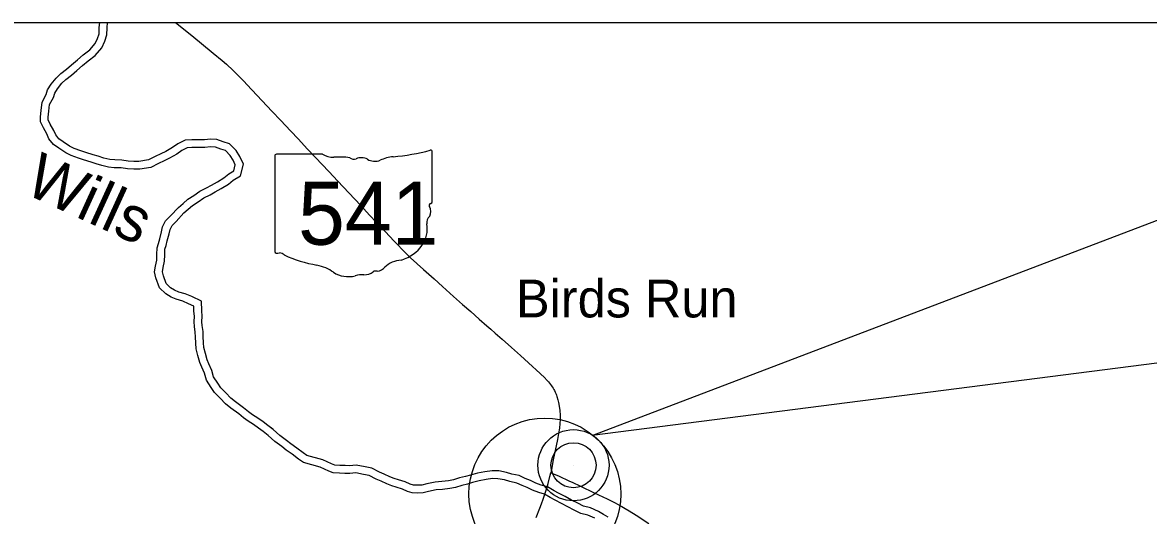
# Model space of a CAD drawing. Extents: x -12.1 to 34, y 0 to 22.
# Drawn here: x 3.941 to 6.151, y 19.34 to 20.306 of the extents above; entities that cross this region are included whole.
import ezdxf

# ---------------------------------------------------------------- set-up
doc = ezdxf.new("R2010")
doc.units = 0
for name, color, linetype in [('BR_P_Gen_Text', 7, 'Continuous'), ('Default', 7, 'Continuous'), ('GM_X_Major_River', 7, 'Continuous'), ('GM_X_Major_River_Text', 7, 'Continuous'), ('GM_X_State_Route', 7, 'Continuous'), ('GM_X_State_Shield', 7, 'Continuous'), ('GM_X_Unincorporated', 7, 'Continuous'), ('GM_X_Unincorporated_Location', 7, 'Continuous'), ('GM_X_Unincorporated_Text', 7, 'Continuous'), ('SH_Text', 7, 'Continuous')]:
    doc.layers.add(name, color=color, linetype=linetype)

msp = doc.modelspace()

# ---------------------------------------------------------------- linework, layer by layer
at = {"layer": 'BR_P_Gen_Text'}
msp.add_lwpolyline([(6.2488, 19.9493), (6.2488, 19.649), (5.0586, 19.4964)], close=True, dxfattribs=at)
at = {"layer": 'Default'}
msp.add_circle((4.9659, 19.3816), 0.149, dxfattribs=at)
at = {"layer": 'GM_X_Major_River'}
for points in [[(4.0372, 20.2236), (4.0485, 20.2333), (4.0601, 20.243), (4.0727, 20.253), (4.0836, 20.2649), (4.0881, 20.2748), (4.0909, 20.2844), (4.0914, 20.2965), (4.0922, 20.3063)], [(4.0472, 20.2121), (4.0584, 20.2217), (4.0697, 20.2312), (4.0832, 20.2419), (4.0965, 20.2564), (4.1025, 20.2696), (4.106, 20.2819), (4.1067, 20.2956), (4.1074, 20.3063)], [(4.0473, 20.2122), (4.0584, 20.2217), (4.0697, 20.2312), (4.0832, 20.2419), (4.0965, 20.2564), (4.1025, 20.2696), (4.106, 20.2819), (4.1067, 20.2956), (4.1074, 20.3063)], [(4.4228, 19.4967), (4.4131, 19.504), (4.4038, 19.5107), (4.3942, 19.5177), (4.3835, 19.5243), (4.3746, 19.531), (4.3653, 19.5387), (4.3496, 19.5503), (4.3393, 19.5583), (4.3285, 19.5696), (4.3178, 19.5805), (4.3113, 19.5907), (4.3016, 19.6051), (4.2979, 19.6186), (4.2925, 19.6306), (4.2885, 19.6398), (4.2848, 19.6536), (4.2819, 19.6663), (4.2807, 19.6773), (4.2802, 19.6897), (4.2798, 19.699), (4.2783, 19.7103), (4.2775, 19.7192), (4.2781, 19.7302), (4.2773, 19.7405), (4.2772, 19.75), (4.2668, 19.7549), (4.2551, 19.7597), (4.2423, 19.7635), (4.2323, 19.768), (4.222, 19.774), (4.2098, 19.7859), (4.2026, 19.8053), (4.2, 19.8174), (4.202, 19.8288), (4.2044, 19.8401), (4.2046, 19.8511), (4.2052, 19.8643), (4.2079, 19.8732), (4.21, 19.882), (4.2137, 19.8956), (4.2158, 19.9055), (4.2217, 19.9173), (4.2315, 19.927), (4.2469, 19.9438), (4.256, 19.9517), (4.2655, 19.9599), (4.2772, 19.9671), (4.2888, 19.9754), (4.3018, 19.9819), (4.3117, 19.9873), (4.3233, 19.9938), (4.336, 20.0014), (4.3455, 20.0093), (4.3553, 20.0154), (4.3584, 20.0272), (4.3541, 20.0364), (4.3483, 20.0455), (4.339, 20.055), (4.3298, 20.0581), (4.3194, 20.0619), (4.3099, 20.0622), (4.2985, 20.0613), (4.2858, 20.0612), (4.2734, 20.0611), (4.2642, 20.0606), (4.2533, 20.0552), (4.2434, 20.0484), (4.229, 20.0401), (4.2187, 20.035), (4.2075, 20.0296), (4.1926, 20.0223), (4.1707, 20.0186), (4.159, 20.0185), (4.1466, 20.0194), (4.1342, 20.021), (4.1207, 20.0216), (4.1097, 20.0226), (4.0966, 20.026), (4.0852, 20.0294), (4.0753, 20.0322), (4.0607, 20.037), (4.0504, 20.0401), (4.0362, 20.0456), (4.0255, 20.0508), (4.0123, 20.0599), (4.0016, 20.0669), (3.9926, 20.0781), (3.9886, 20.088), (3.9818, 20.1), (3.976, 20.1117), (3.9759, 20.1212), (3.9772, 20.134), (3.9792, 20.15), (3.9872, 20.1653), (3.9899, 20.1742), (3.9969, 20.1853), (4.0067, 20.1974), (4.0158, 20.2064), (4.0274, 20.215), (4.0372, 20.2236)], [(4.432, 19.5088), (4.4222, 19.5163), (4.4128, 19.523), (4.4027, 19.5303), (4.3921, 19.5369), (4.384, 19.5429), (4.3747, 19.5507), (4.3588, 19.5624), (4.3495, 19.5696), (4.3395, 19.5802), (4.3298, 19.59), (4.3241, 19.599), (4.3157, 19.6115), (4.3123, 19.6238), (4.3064, 19.6368), (4.3029, 19.6448), (4.2996, 19.6573), (4.2969, 19.6689), (4.2959, 19.6784), (4.2955, 19.6904), (4.295, 19.7003), (4.2934, 19.712), (4.2927, 19.7194), (4.2933, 19.7304), (4.2925, 19.7411), (4.2923, 19.7597), (4.273, 19.7688), (4.2602, 19.7741), (4.2476, 19.7778), (4.2393, 19.7816), (4.2313, 19.7862), (4.2229, 19.7944), (4.2172, 19.8096), (4.2155, 19.8177), (4.217, 19.8259), (4.2196, 19.8384), (4.2198, 19.8506), (4.2203, 19.8616), (4.2227, 19.8692), (4.2247, 19.8783), (4.2286, 19.892), (4.2303, 19.9005), (4.2342, 19.9082), (4.2425, 19.9164), (4.2576, 19.9329), (4.266, 19.9402), (4.2746, 19.9477), (4.2856, 19.9545), (4.2967, 19.9623), (4.3089, 19.9685), (4.3191, 19.974), (4.3309, 19.9807), (4.3448, 19.989), (4.3544, 19.997), (4.3685, 20.0057), (4.3746, 20.0287), (4.3675, 20.0437), (4.3603, 20.055), (4.3473, 20.0683), (4.3348, 20.0725), (4.3224, 20.077), (4.3095, 20.0774), (4.2979, 20.0765), (4.2856, 20.0764), (4.273, 20.0763), (4.2603, 20.0757), (4.2455, 20.0683), (4.2352, 20.0612), (4.2218, 20.0535), (4.212, 20.0487), (4.2008, 20.0433), (4.1879, 20.037), (4.1693, 20.0338), (4.1595, 20.0337), (4.1482, 20.0345), (4.1355, 20.0362), (4.1217, 20.0368), (4.1123, 20.0376), (4.1007, 20.0406), (4.0895, 20.044), (4.0797, 20.0467), (4.0653, 20.0515), (4.0554, 20.0545), (4.0423, 20.0595), (4.0332, 20.064), (4.0208, 20.0725), (4.012, 20.0783), (4.0059, 20.0859), (4.0024, 20.0947), (3.9952, 20.1072), (3.9912, 20.1153), (3.9912, 20.1206), (3.9923, 20.1323), (3.994, 20.1454), (4.0013, 20.1595), (4.0039, 20.1678), (4.0093, 20.1764), (4.018, 20.1872), (4.0258, 20.1948), (4.037, 20.2032), (4.0473, 20.2122)], [(4.4325, 19.5084), (4.4222, 19.5163), (4.4128, 19.523), (4.4027, 19.5303), (4.3921, 19.5369), (4.384, 19.5429), (4.3747, 19.5507), (4.3588, 19.5624), (4.3495, 19.5696), (4.3395, 19.5802), (4.3298, 19.59), (4.3241, 19.599), (4.3157, 19.6115), (4.3123, 19.6238), (4.3064, 19.6368), (4.3029, 19.6448), (4.2996, 19.6573), (4.2969, 19.6689), (4.2959, 19.6784), (4.2955, 19.6904), (4.295, 19.7003), (4.2934, 19.712), (4.2927, 19.7194), (4.2933, 19.7304), (4.2925, 19.7411), (4.2923, 19.7597), (4.273, 19.7688), (4.2602, 19.7741), (4.2476, 19.7778), (4.2393, 19.7816), (4.2313, 19.7862), (4.2229, 19.7944), (4.2172, 19.8096), (4.2155, 19.8177), (4.217, 19.8259), (4.2196, 19.8384), (4.2198, 19.8506), (4.2203, 19.8616), (4.2227, 19.8692), (4.2247, 19.8783), (4.2286, 19.892), (4.2303, 19.9005), (4.2342, 19.9082), (4.2425, 19.9164), (4.2576, 19.9329), (4.266, 19.9402), (4.2746, 19.9477), (4.2856, 19.9545), (4.2967, 19.9623), (4.3089, 19.9685), (4.3191, 19.974), (4.3309, 19.9807), (4.3448, 19.989), (4.3544, 19.997), (4.3685, 20.0057), (4.3746, 20.0287), (4.3675, 20.0437), (4.3603, 20.055), (4.3473, 20.0683), (4.3348, 20.0725), (4.3224, 20.077), (4.3095, 20.0774), (4.2979, 20.0765), (4.2856, 20.0764), (4.273, 20.0763), (4.2603, 20.0757), (4.2455, 20.0683), (4.2352, 20.0612), (4.2218, 20.0535), (4.212, 20.0487), (4.2008, 20.0433), (4.1879, 20.037), (4.1693, 20.0338), (4.1595, 20.0337), (4.1482, 20.0345), (4.1355, 20.0362), (4.1217, 20.0368), (4.1123, 20.0376), (4.1007, 20.0406), (4.0895, 20.044), (4.0797, 20.0467), (4.0653, 20.0515), (4.0554, 20.0545), (4.0423, 20.0595), (4.0332, 20.064), (4.0208, 20.0725), (4.012, 20.0783), (4.0059, 20.0859), (4.0024, 20.0947), (3.9952, 20.1072), (3.9912, 20.1153), (3.9912, 20.1206), (3.9923, 20.1323), (3.994, 20.1454), (4.0013, 20.1595), (4.0039, 20.1678), (4.0093, 20.1764), (4.018, 20.1872), (4.0258, 20.1948), (4.037, 20.2032), (4.0473, 20.2122)], [(5.0638, 19.3341), (5.0503, 19.3403), (5.0368, 19.3434), (5.0237, 19.35), (5.0108, 19.3563), (4.9987, 19.3632), (4.9859, 19.3695), (4.9766, 19.3747), (4.9649, 19.3814), (4.9539, 19.3845), (4.9418, 19.3889), (4.9315, 19.3945), (4.9211, 19.3983), (4.9108, 19.4032), (4.8973, 19.4059), (4.887, 19.4094), (4.8739, 19.4117), (4.8633, 19.412), (4.8505, 19.4104), (4.8371, 19.4074), (4.824, 19.4041), (4.8138, 19.4012), (4.8028, 19.3986), (4.7904, 19.3946), (4.7791, 19.3927), (4.7653, 19.3907), (4.7529, 19.3896), (4.7377, 19.3869), (4.7268, 19.384), (4.7151, 19.3835), (4.7055, 19.3841), (4.6963, 19.3865), (4.6863, 19.391), (4.6742, 19.3948), (4.6653, 19.3979), (4.6561, 19.4014), (4.6444, 19.4066), (4.6351, 19.4108), (4.6212, 19.4177), (4.6099, 19.4201), (4.595, 19.4231), (4.5833, 19.422), (4.5734, 19.4222), (4.5631, 19.4225), (4.5507, 19.4234), (4.5418, 19.4265), (4.5251, 19.4342), (4.492, 19.4434), (4.4827, 19.4497), (4.4699, 19.4595), (4.4585, 19.4676), (4.4495, 19.4746), (4.4363, 19.4847), (4.4228, 19.4967)], [(5.0901, 19.3363), (5.0809, 19.3416), (5.071, 19.3475), (5.0553, 19.3548), (5.042, 19.3578), (5.0304, 19.3636), (5.018, 19.3697), (5.0059, 19.3767), (4.993, 19.383), (4.9842, 19.388), (4.9708, 19.3955), (4.9586, 19.3989), (4.9481, 19.4029), (4.9378, 19.4084), (4.9271, 19.4124), (4.9157, 19.4178), (4.9013, 19.4206), (4.8908, 19.4241), (4.8754, 19.4269), (4.8625, 19.4272), (4.848, 19.4254), (4.8336, 19.4223), (4.82, 19.4188), (4.8099, 19.4159), (4.7987, 19.4133), (4.7868, 19.4094), (4.7768, 19.4077), (4.7636, 19.4059), (4.7509, 19.4047), (4.7344, 19.4018), (4.7245, 19.3991), (4.7153, 19.3988), (4.7079, 19.3992), (4.7014, 19.4009), (4.6918, 19.4053), (4.679, 19.4093), (4.6705, 19.4122), (4.6619, 19.4155), (4.6506, 19.4205), (4.6417, 19.4245), (4.6263, 19.4322), (4.613, 19.435), (4.5957, 19.4385), (4.5827, 19.4372), (4.5737, 19.4374), (4.5638, 19.4377), (4.5538, 19.4384), (4.5475, 19.4407), (4.5303, 19.4485), (4.4985, 19.4574), (4.4917, 19.4621), (4.4789, 19.4718), (4.4676, 19.4798), (4.4589, 19.4866), (4.446, 19.4965), (4.4325, 19.5084)], [(5.0901, 19.3363), (5.0809, 19.3416), (5.071, 19.3475), (5.0553, 19.3548), (5.042, 19.3578), (5.0304, 19.3636), (5.018, 19.3697), (5.0059, 19.3767), (4.993, 19.383), (4.9842, 19.388), (4.9708, 19.3955), (4.9586, 19.3989), (4.9481, 19.4029), (4.9378, 19.4084), (4.9271, 19.4124), (4.9157, 19.4178), (4.9013, 19.4206), (4.8908, 19.4241), (4.8754, 19.4269), (4.8625, 19.4272), (4.848, 19.4254), (4.8336, 19.4223), (4.82, 19.4188), (4.8099, 19.4159), (4.7987, 19.4133), (4.7868, 19.4094), (4.7768, 19.4077), (4.7636, 19.4059), (4.7509, 19.4047), (4.7344, 19.4018), (4.7245, 19.3991), (4.7153, 19.3988), (4.7079, 19.3992), (4.7014, 19.4009), (4.6918, 19.4053), (4.679, 19.4093), (4.6705, 19.4122), (4.6619, 19.4155), (4.6506, 19.4205), (4.6417, 19.4245), (4.6263, 19.4322), (4.613, 19.435), (4.5957, 19.4385), (4.5827, 19.4372), (4.5737, 19.4374), (4.5638, 19.4377), (4.5538, 19.4384), (4.5475, 19.4407), (4.5303, 19.4485), (4.4985, 19.4574), (4.4917, 19.4621), (4.4789, 19.4718), (4.4676, 19.4798), (4.4589, 19.4866), (4.446, 19.4965), (4.4328, 19.5081)]]:
    msp.add_lwpolyline(points, dxfattribs=at)
at = {"layer": 'GM_X_State_Route'}
for points in [[(4.2413, 20.3063), (4.2728, 20.2807), (4.3151, 20.2461), (4.3327, 20.2316), (4.3411, 20.2244), (4.3539, 20.2124), (4.3626, 20.2039), (4.3708, 20.1956), (4.3752, 20.191), (4.3817, 20.1843), (4.4302, 20.1324), (4.4475, 20.1142), (4.4667, 20.094), (4.4822, 20.0773), (4.4997, 20.0585), (4.5156, 20.0416), (4.5418, 20.0142), (4.5598, 19.9951), (4.5814, 19.9723), (4.605, 19.9473), (4.622, 19.9288), (4.6358, 19.9139), (4.653, 19.8957), (4.6698, 19.8779), (4.6739, 19.8737), (4.6893, 19.8579), (4.703, 19.8445), (4.7143, 19.8341), (4.7154, 19.833), (4.7275, 19.8221), (4.7484, 19.8036), (4.7649, 19.7888), (4.7865, 19.7693), (4.8044, 19.7536), (4.8205, 19.7393), (4.8371, 19.7246), (4.8521, 19.7117), (4.8599, 19.7048), (4.8682, 19.6974), (4.8822, 19.6851), (4.9006, 19.669), (4.9183, 19.653), (4.9337, 19.6388), (4.9567, 19.6182), (4.9582, 19.6167), (4.9647, 19.6105), (4.9707, 19.6041), (4.973, 19.6017), (4.975, 19.5993), (4.9772, 19.5966), (4.979, 19.5941), (4.9805, 19.5918), (4.9821, 19.5892), (4.9834, 19.5869), (4.9846, 19.5846), (4.986, 19.5817), (4.9873, 19.5787), (4.9879, 19.5772)], [(4.9879, 19.5772), (4.9886, 19.5757), (4.9896, 19.5727), (4.9916, 19.5665), (4.9928, 19.5614), (4.9942, 19.5539), (4.9951, 19.5457), (4.9957, 19.5364), (4.9958, 19.532), (4.9957, 19.5276), (4.9954, 19.52), (4.9944, 19.5107), (4.9928, 19.5002), (4.9907, 19.4888), (4.9825, 19.4488), (4.9791, 19.43), (4.9779, 19.423)], [(4.9487, 19.3354), (4.9563, 19.354), (4.9592, 19.3621), (4.9627, 19.3717), (4.9659, 19.3816), (4.9696, 19.3933), (4.9721, 19.402), (4.976, 19.4161), (4.9779, 19.423)], [(4.9779, 19.423), (4.9925, 19.417), (5.0145, 19.4071), (5.0196, 19.4048), (5.0359, 19.3971), (5.0627, 19.3842), (5.088, 19.3722), (5.0999, 19.3661), (5.1123, 19.3595), (5.1315, 19.3485), (5.1454, 19.34), (5.1703, 19.3237)]]:
    msp.add_lwpolyline(points, dxfattribs=at)
at = {"layer": 'GM_X_State_Shield'}
for p, q in [((4.4359, 20.0449), (4.4359, 19.8573)), ((4.5295, 20.0481), (4.439, 20.0481)), ((4.7449, 19.9546), (4.7449, 20.0528)), ((4.7449, 19.9547), (4.7449, 19.9546))]:
    msp.add_line(p, q, dxfattribs=at)
for centre, major_axis, start_param, end_param in [((4.4395, 20.0453), (0.00358, 0), 1.712693, 3.28349), ((4.551, 20.0699), (0.0347, 0), 4.042523, 4.731795), ((4.5625, 19.9428), (0.1246, 0), 1.404758, 1.657858), ((4.6766, 19.9908), (0.0659, 0), 1.699011, 2.107814), ((4.6348, 20.3039), (0.3277, 0), 4.814394, 5.042369), ((4.7415, 20.0532), (0.00344, 0), 6.141152, 7.989035), ((4.5908, 20.0463), (0.01, 0), 3.836095, 5.185415), ((4.6055, 20.0246), (0.0208, 0), 0.950623, 2.079405), ((4.6324, 20.0543), (0.0251, 0), 4.081561, 5.145723), ((4.7412, 19.9543), (0.00368, 0), 5.05454, 6.418171), ((4.7441, 19.9474), (0.00532, 0), 1.883978, 3.671073), ((4.7102, 19.935), (0.032, 0), 5.934695, 6.695948), ((4.6532, 19.9011), (0.082, 0), 5.101752, 6.440018), ((4.7572, 19.9136), (0.0232, 0), 2.387724, 3.262537), ((4.4395, 19.8569), (0.00361, 0), 3.00124, 4.508301), ((4.44, 19.8761), (0.0276, 0), 4.665946, 4.897461), ((4.4457, 19.8465), (0.00994, 0), 0.519207, 1.627899), ((4.5711, 20.015), (0.2366, 0), 4.195997, 4.488961), ((4.5006, 19.773), (0.074, 0), 0.823519, 1.323587), ((4.6309, 19.8391), (0.0265, 0), 4.937069, 5.64225), ((4.6878, 19.8046), (0.0449, 0), 1.647645, 2.488434), ((4.5807, 19.8455), (0.047, 0), 4.026481, 4.996735), ((4.6078, 19.7807), (0.0386, 0), 1.495662, 1.94098), ((4.6112, 19.8315), (0.025, 0), 4.691044, 5.507374), ((4.6339, 19.8133), (0.00705, 0), 1.147584, 2.315152)]:
    msp.add_ellipse(centre, major_axis=major_axis, ratio=0.8, start_param=start_param, end_param=end_param, dxfattribs=at)
at = {"layer": 'GM_X_Unincorporated'}
for radius in [0.0698, 0.0442]:
    msp.add_circle((5.0221, 19.4381), radius, dxfattribs=at)
at = {"layer": 'GM_X_Unincorporated_Location'}
msp.add_line((5.0221, 19.4381), (5.0221, 19.4381), dxfattribs=at)
at = {"layer": 'SH_Text'}
msp.add_lwpolyline([(2.8817, 20.3063), (10.5897, 20.3063), (10.5897, 10.9773), (2.8817, 10.9773)], close=True, dxfattribs=at)

# ---------------------------------------------------------------- texts
at = {"layer": 'GM_X_Major_River_Text'}
msp.add_text('Wills', height=0.08874, rotation=335.4321, dxfattribs=at).set_placement((3.9409, 19.9728))
at = {"layer": 'GM_X_State_Shield'}
msp.add_text('541', height=0.1236, dxfattribs=at).set_placement((4.4815, 19.8705))
at = {"layer": 'GM_X_Unincorporated_Text'}
msp.add_text('Birds Run', height=0.07404, rotation=0, dxfattribs=at).set_placement((4.9093, 19.728))

doc.saveas('drawing.dxf')
